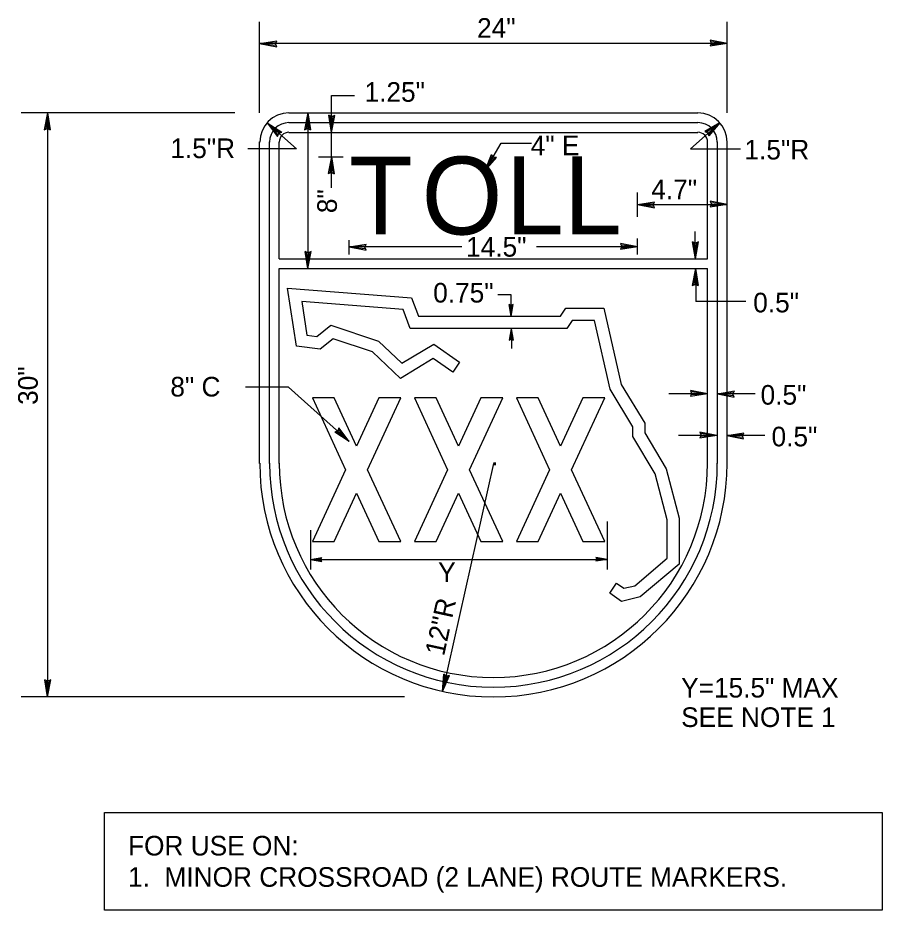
# Model space of a CAD drawing. Extents: x 52194 to 54069, y 8993 to 10153.
# Drawn here: x 52359.7 to 52729.7, y 9460.7 to 9842.7 of the extents above; entities that cross this region are included whole.
import ezdxf

# ---------------------------------------------------------------- set-up
doc = ezdxf.new("R2010")
doc.units = 0
for name, color, linetype in [('GSDims', 7, 'Continuous'), ('SignPanel', 7, 'Continuous'), ('TextLabel', 7, 'Continuous')]:
    doc.layers.add(name, color=color, linetype=linetype)

msp = doc.modelspace()

# ---------------------------------------------------------------- linework, layer by layer
at = {"layer": 'GSDims'}
for p, q in [((52463.23, 9802.06), (52463.23, 9840.96)), ((52663.33, 9802.06), (52663.33, 9840.96)), ((52463.23, 9831.66), (52470.53, 9832.86)), ((52463.23, 9831.66), (52470.23, 9832.16)), ((52663.33, 9831.66), (52463.23, 9831.66)), ((52463.23, 9831.66), (52470.53, 9830.26)), ((52463.23, 9831.66), (52470.23, 9830.96)), ((52470.03, 9831.56), (52470.53, 9832.86)), ((52470.53, 9830.26), (52470.03, 9831.56)), ((52663.33, 9831.66), (52656.03, 9833.06)), ((52656.03, 9833.06), (52656.53, 9831.76)), ((52656.53, 9831.76), (52656.03, 9830.56)), ((52663.33, 9831.66), (52656.03, 9830.56)), ((52663.33, 9831.66), (52656.33, 9832.46)), ((52663.33, 9831.66), (52656.33, 9831.16)), ((52493.98, 9793.66), (52493.98, 9809.41)), ((52493.98, 9809.41), (52503.83, 9809.41)), ((52452.58, 9802.06), (52361.21, 9802.06)), ((52372.46, 9802.06), (52371.06, 9794.81)), ((52372.46, 9802.06), (52371.71, 9795.06)), ((52372.46, 9802.06), (52372.46, 9552.01)), ((52372.46, 9802.06), (52373.61, 9794.76)), ((52372.46, 9802.06), (52372.96, 9795.06)), ((52483.83, 9802.06), (52482.43, 9794.81)), ((52483.83, 9802.06), (52483.08, 9795.06)), ((52483.83, 9802.06), (52483.83, 9735.36)), ((52483.83, 9802.06), (52484.98, 9794.76)), ((52483.83, 9802.06), (52484.33, 9795.06)), ((52493.98, 9793.66), (52492.83, 9800.96)), ((52494.08, 9800.41), (52492.83, 9800.96)), ((52493.98, 9793.66), (52495.38, 9800.91)), ((52495.38, 9800.91), (52494.08, 9800.41)), ((52663.33, 9802.06), (52663.33, 9802.06)), ((52466.43, 9797.81), (52478.98, 9786.66)), ((52466.43, 9797.81), (52472.68, 9793.81)), ((52466.43, 9797.81), (52470.93, 9791.91)), ((52466.43, 9797.81), (52471.18, 9792.61)), ((52466.43, 9797.81), (52471.98, 9793.51)), ((52466.43, 9797.81), (52472.68, 9793.81)), ((52466.43, 9797.81), (52470.93, 9791.91)), ((52466.43, 9797.81), (52471.18, 9792.61)), ((52466.43, 9797.81), (52471.98, 9793.51)), ((52493.98, 9793.66), (52493.48, 9800.66)), ((52493.98, 9793.66), (52494.73, 9800.66)), ((52660.13, 9797.81), (52647.58, 9786.66)), ((52660.13, 9797.81), (52653.78, 9794.06)), ((52660.13, 9797.81), (52654.43, 9793.71)), ((52660.13, 9797.81), (52655.23, 9792.81)), ((52660.13, 9797.81), (52655.43, 9792.11)), ((52371.06, 9794.81), (52372.36, 9795.31)), ((52372.36, 9795.31), (52373.61, 9794.76)), ((52470.93, 9791.91), (52471.38, 9793.26)), ((52470.93, 9791.91), (52471.38, 9793.26)), ((52471.38, 9793.26), (52472.68, 9793.81)), ((52471.38, 9793.26), (52472.68, 9793.81)), ((52482.43, 9794.81), (52483.73, 9795.31)), ((52483.73, 9795.31), (52484.98, 9794.76)), ((52493.98, 9783.26), (52493.98, 9793.66)), ((52653.78, 9794.06), (52655.03, 9793.41)), ((52655.03, 9793.41), (52655.43, 9792.11)), ((52478.98, 9786.66), (52458.13, 9786.66)), ((52559.78, 9777.31), (52566.63, 9789.11)), ((52566.63, 9789.11), (52579.61, 9789.11)), ((52647.58, 9786.66), (52669.08, 9786.66)), ((52488.48, 9783.26), (52498.93, 9783.26)), ((52493.98, 9783.26), (52492.58, 9776.01)), ((52493.98, 9783.26), (52493.23, 9776.26)), ((52493.98, 9769.96), (52493.98, 9783.26)), ((52493.98, 9783.26), (52495.13, 9775.96)), ((52493.98, 9783.26), (52494.48, 9776.26)), ((52559.78, 9777.31), (52562.43, 9784.21)), ((52559.78, 9777.31), (52562.88, 9783.61)), ((52559.78, 9777.31), (52563.93, 9782.96)), ((52559.78, 9777.31), (52564.63, 9782.91)), ((52563.28, 9783.06), (52562.43, 9784.21)), ((52564.63, 9782.91), (52563.28, 9783.06)), ((52492.58, 9776.01), (52493.88, 9776.51)), ((52493.88, 9776.51), (52495.13, 9775.96)), ((52624.93, 9757.51), (52624.93, 9767.96)), ((52624.93, 9762.76), (52632.23, 9763.91)), ((52624.93, 9762.76), (52631.93, 9763.26)), ((52624.93, 9762.76), (52663.33, 9762.76)), ((52624.93, 9762.76), (52632.18, 9761.36)), ((52624.93, 9762.76), (52631.93, 9762.01)), ((52631.68, 9762.66), (52632.23, 9763.91)), ((52632.18, 9761.36), (52631.68, 9762.66)), ((52656.58, 9762.86), (52656.03, 9761.61)), ((52663.33, 9762.76), (52656.03, 9761.61)), ((52663.33, 9762.76), (52656.08, 9764.16)), ((52656.08, 9764.16), (52656.58, 9762.86)), ((52663.33, 9762.76), (52656.33, 9763.51)), ((52663.33, 9762.76), (52656.33, 9762.26)), ((52501.53, 9741.36), (52501.53, 9747.56)), ((52624.93, 9741.36), (52624.93, 9748.26)), ((52649.78, 9739.51), (52649.68, 9751.16)), ((52501.53, 9744.66), (52508.83, 9745.81)), ((52501.53, 9744.66), (52508.53, 9745.16)), ((52501.53, 9744.66), (52508.78, 9743.26)), ((52501.53, 9744.66), (52508.53, 9743.91)), ((52549.76, 9744.66), (52501.53, 9744.66)), ((52508.28, 9744.56), (52508.83, 9745.81)), ((52508.78, 9743.26), (52508.28, 9744.56)), ((52624.93, 9744.66), (52581.72, 9744.66)), ((52618.18, 9744.76), (52617.63, 9743.51)), ((52624.93, 9744.66), (52617.63, 9743.51)), ((52624.93, 9744.66), (52617.68, 9746.06)), ((52617.68, 9746.06), (52618.18, 9744.76)), ((52624.93, 9744.66), (52617.93, 9745.41)), ((52624.93, 9744.66), (52617.93, 9744.16)), ((52649.78, 9739.51), (52648.48, 9746.81)), ((52649.78, 9746.21), (52648.48, 9746.81)), ((52649.78, 9739.51), (52649.18, 9746.51)), ((52649.78, 9739.51), (52651.08, 9746.81)), ((52651.08, 9746.81), (52649.78, 9746.21)), ((52649.78, 9739.51), (52650.38, 9746.51)), ((52483.83, 9735.36), (52482.68, 9742.66)), ((52483.93, 9742.11), (52482.68, 9742.66)), ((52483.83, 9735.36), (52483.33, 9742.36)), ((52483.83, 9735.36), (52485.23, 9742.61)), ((52483.83, 9735.36), (52484.58, 9742.36)), ((52485.23, 9742.61), (52483.93, 9742.11)), ((52649.78, 9735.36), (52648.38, 9728.06)), ((52649.78, 9735.36), (52649.08, 9728.36)), ((52649.78, 9735.36), (52650.98, 9728.06)), ((52649.78, 9735.36), (52650.28, 9728.36)), ((52649.78, 9735.36), (52649.93, 9721.26)), ((52648.38, 9728.06), (52649.68, 9728.56)), ((52649.68, 9728.56), (52650.98, 9728.06)), ((52570.88, 9724.16), (52565.13, 9724.16)), ((52570.88, 9715.01), (52570.88, 9724.16)), ((52671.38, 9721.26), (52649.93, 9721.26)), ((52570.88, 9715.01), (52570.08, 9719.91)), ((52570.88, 9719.51), (52570.08, 9719.91)), ((52570.88, 9715.01), (52570.48, 9719.71)), ((52570.88, 9715.01), (52571.78, 9719.91)), ((52571.78, 9719.91), (52570.88, 9719.51)), ((52570.88, 9715.01), (52571.28, 9719.71)), ((52570.88, 9709.61), (52569.98, 9704.71)), ((52570.88, 9709.61), (52570.48, 9704.91)), ((52570.88, 9709.61), (52570.98, 9701.21)), ((52570.88, 9709.61), (52571.68, 9704.71)), ((52570.88, 9709.61), (52571.28, 9704.91)), ((52569.98, 9704.71), (52570.88, 9705.11)), ((52570.88, 9705.11), (52571.68, 9704.71)), ((52475.63, 9684.55), (52457.23, 9684.55)), ((52501.59, 9661.29), (52475.63, 9684.55)), ((52654.93, 9681.76), (52647.63, 9683.16)), ((52647.63, 9683.16), (52648.13, 9681.86)), ((52654.93, 9681.76), (52647.93, 9682.56)), ((52659.13, 9681.76), (52666.43, 9682.96)), ((52665.83, 9681.66), (52666.43, 9682.96)), ((52654.93, 9681.76), (52638.43, 9681.76)), ((52648.13, 9681.86), (52647.63, 9680.66)), ((52654.93, 9681.76), (52647.63, 9680.66)), ((52654.93, 9681.76), (52647.93, 9681.26)), ((52659.13, 9681.76), (52666.13, 9682.26)), ((52659.13, 9681.76), (52666.33, 9680.36)), ((52659.13, 9681.76), (52666.13, 9681.06)), ((52675.38, 9681.76), (52659.13, 9681.76)), ((52666.33, 9680.36), (52665.83, 9681.66)), ((52497.12, 9667.19), (52496.66, 9665.87)), ((52501.59, 9661.29), (52497.12, 9667.19)), ((52496.66, 9665.87), (52495.38, 9665.31)), ((52501.59, 9661.29), (52495.38, 9665.31)), ((52501.59, 9661.29), (52496.05, 9665.6)), ((52501.59, 9661.29), (52496.88, 9666.5)), ((52658.98, 9663.91), (52642.48, 9663.91)), ((52658.98, 9663.91), (52651.68, 9665.31)), ((52651.68, 9665.31), (52652.18, 9664.01)), ((52652.18, 9664.01), (52651.68, 9662.81)), ((52658.98, 9663.91), (52651.68, 9662.81)), ((52658.98, 9663.91), (52651.98, 9664.71)), ((52658.98, 9663.91), (52651.98, 9663.41)), ((52663.18, 9663.91), (52670.48, 9665.11)), ((52663.18, 9663.91), (52670.18, 9664.41)), ((52663.18, 9663.91), (52670.38, 9662.51)), ((52663.18, 9663.91), (52670.18, 9663.21)), ((52679.43, 9663.91), (52663.18, 9663.91)), ((52669.88, 9663.81), (52670.48, 9665.11)), ((52670.38, 9662.51), (52669.88, 9663.81)), ((52563.33, 9651.96), (52541.53, 9554.36)), ((52563.33, 9651.96), (52563.33, 9651.96)), ((52611.96, 9627.06), (52611.96, 9606.57)), ((52484.99, 9623.44), (52484.99, 9606.57)), ((52484.99, 9610.88), (52489.86, 9611.63)), ((52484.99, 9610.88), (52489.66, 9611.19)), ((52484.99, 9610.88), (52489.86, 9610)), ((52484.99, 9610.88), (52489.66, 9610.44)), ((52484.99, 9610.88), (52538.09, 9610.88)), ((52489.46, 9610.82), (52489.86, 9611.63)), ((52489.86, 9610), (52489.46, 9610.82)), ((52538.09, 9610.88), (52611.96, 9610.88)), ((52611.96, 9610.88), (52607.09, 9611.75)), ((52607.09, 9611.75), (52607.49, 9610.94)), ((52607.49, 9610.94), (52607.09, 9610.13)), ((52611.96, 9610.88), (52607.09, 9610.13)), ((52611.96, 9610.88), (52607.29, 9611.32)), ((52611.96, 9610.88), (52607.29, 9610.57)), ((52541.53, 9554.36), (52542.03, 9561.76)), ((52541.53, 9554.36), (52542.63, 9561.36)), ((52541.53, 9554.36), (52544.53, 9561.16)), ((52541.53, 9554.36), (52543.83, 9561.06)), ((52543.13, 9560.96), (52542.03, 9561.76)), ((52544.53, 9561.16), (52543.13, 9560.96)), ((52372.46, 9552.01), (52371.31, 9559.31)), ((52372.56, 9558.76), (52371.31, 9559.31)), ((52372.46, 9552.01), (52371.96, 9559.01)), ((52372.46, 9552.01), (52373.86, 9559.26)), ((52372.46, 9552.01), (52373.21, 9559.01)), ((52373.86, 9559.26), (52372.56, 9558.76)), ((52525.18, 9552.01), (52361.21, 9552.01))]:
    msp.add_line(p, q, dxfattribs=at)
at = {"layer": 'SignPanel'}
for p, q in [((52475.73, 9802.06), (52650.83, 9802.06)), ((52475.73, 9797.86), (52650.83, 9797.86)), ((52475.73, 9793.66), (52650.83, 9793.66)), ((52463.23, 9651.96), (52463.23, 9789.56)), ((52467.43, 9651.96), (52467.43, 9789.56)), ((52471.53, 9739.56), (52471.53, 9789.56)), ((52654.93, 9739.56), (52654.93, 9789.56)), ((52659.13, 9651.96), (52659.13, 9789.56)), ((52663.33, 9651.96), (52663.33, 9789.56)), ((52471.53, 9739.56), (52654.93, 9739.56)), ((52471.53, 9651.96), (52471.53, 9735.36)), ((52471.53, 9735.36), (52654.93, 9735.36)), ((52654.93, 9651.96), (52654.93, 9735.36)), ((52475.21, 9726.98), (52528.21, 9722.78)), ((52478.98, 9702.13), (52475.21, 9726.98)), ((52524.61, 9717.81), (52481.25, 9721.24)), ((52481.25, 9721.24), (52483.44, 9706.84)), ((52528.21, 9722.78), (52531.17, 9714.97)), ((52527.68, 9709.73), (52524.61, 9717.81)), ((52591.96, 9714.97), (52594.25, 9718.44)), ((52594.25, 9718.44), (52610.61, 9718.44)), ((52610.61, 9718.44), (52618.01, 9685.78)), ((52531.17, 9714.97), (52591.96, 9714.97)), ((52596.97, 9713.2), (52594.68, 9709.73)), ((52606.55, 9713.2), (52596.97, 9713.2)), ((52613.23, 9683.75), (52606.55, 9713.2)), ((52487.64, 9706.31), (52493.66, 9711.17)), ((52493.66, 9711.17), (52514.11, 9704.35)), ((52594.68, 9709.73), (52527.68, 9709.73)), ((52483.44, 9706.84), (52487.64, 9706.31)), ((52489.13, 9700.84), (52478.98, 9702.13)), ((52494.68, 9705.32), (52489.13, 9700.84)), ((52511.46, 9699.72), (52494.68, 9705.32)), ((52514.11, 9704.35), (52524.15, 9694.82)), ((52524.15, 9694.82), (52537.75, 9703.01)), ((52537.75, 9703.01), (52548.82, 9695.34)), ((52523.46, 9688.33), (52511.46, 9699.72)), ((52537.56, 9696.82), (52523.46, 9688.33)), ((52545.96, 9691), (52537.56, 9696.82)), ((52548.82, 9695.34), (52545.96, 9691)), ((52622.98, 9667.68), (52613.23, 9683.75)), ((52618.01, 9685.78), (52628.09, 9669.18)), ((52495.12, 9680), (52485.78, 9680)), ((52485.78, 9680), (52500.03, 9649.27)), ((52504.69, 9659.35), (52495.12, 9680)), ((52514.27, 9680), (52504.69, 9659.35)), ((52509.36, 9649.27), (52523.61, 9680)), ((52523.61, 9680), (52514.27, 9680)), ((52538.78, 9680), (52529.44, 9680)), ((52529.44, 9680), (52543.68, 9649.27)), ((52548.35, 9659.35), (52538.78, 9680)), ((52557.93, 9680), (52548.35, 9659.35)), ((52553.02, 9649.27), (52567.27, 9680)), ((52567.27, 9680), (52557.93, 9680)), ((52582.44, 9680), (52573.1, 9680)), ((52573.1, 9680), (52587.34, 9649.27)), ((52592.01, 9659.35), (52582.44, 9680)), ((52601.59, 9680), (52592.01, 9659.35)), ((52596.68, 9649.27), (52610.93, 9680)), ((52610.93, 9680), (52601.59, 9680)), ((52622.98, 9663.52), (52622.98, 9667.68)), ((52628.09, 9669.18), (52628.09, 9664.99)), ((52632.47, 9647.51), (52622.98, 9663.52)), ((52628.09, 9664.99), (52637.21, 9649.6)), ((52500.03, 9649.27), (52485.78, 9618.54)), ((52523.61, 9618.54), (52509.36, 9649.27)), ((52543.68, 9649.27), (52529.44, 9618.54)), ((52567.27, 9618.54), (52553.02, 9649.27)), ((52587.34, 9649.27), (52573.1, 9618.54)), ((52610.93, 9618.54), (52596.68, 9649.27)), ((52637.21, 9649.6), (52642.83, 9628.54)), ((52637.72, 9627.84), (52632.47, 9647.51)), ((52495.12, 9618.54), (52504.7, 9639.2)), ((52504.7, 9639.2), (52514.27, 9618.54)), ((52538.78, 9618.54), (52548.35, 9639.2)), ((52548.35, 9639.2), (52557.93, 9618.54)), ((52582.44, 9618.54), (52592.01, 9639.2)), ((52592.01, 9639.2), (52601.59, 9618.54)), ((52637.72, 9611.35), (52637.72, 9627.84)), ((52642.83, 9628.54), (52642.83, 9608.87)), ((52485.78, 9618.54), (52495.12, 9618.54)), ((52514.27, 9618.54), (52523.61, 9618.54)), ((52529.44, 9618.54), (52538.78, 9618.54)), ((52557.93, 9618.54), (52567.27, 9618.54)), ((52573.1, 9618.54), (52582.44, 9618.54)), ((52601.59, 9618.54), (52610.93, 9618.54)), ((52623.76, 9599.62), (52637.72, 9611.35)), ((52642.83, 9608.87), (52626.09, 9594.81)), ((52613.1, 9596.44), (52616.01, 9600.74)), ((52616.01, 9600.74), (52619.17, 9598.5)), ((52619.17, 9598.5), (52623.76, 9599.62)), ((52618.14, 9592.85), (52613.1, 9596.44)), ((52626.09, 9594.81), (52618.14, 9592.85))]:
    msp.add_line(p, q, dxfattribs=at)
for centre, radius, start, end in [((52475.78, 9789.51), 12.5, 90, 180), ((52650.78, 9789.51), 12.5, 0, 90), ((52475.78, 9789.51), 8.33, 90, 180), ((52650.78, 9789.51), 8.33, 0, 90), ((52475.78, 9789.51), 4.17, 90, 180), ((52650.78, 9789.51), 4.17, 0, 90), ((52563.28, 9652.01), 100, 180, 0), ((52563.28, 9652.01), 95.83, 180, 0), ((52563.28, 9652.01), 91.67, 180, 0)]:
    msp.add_arc(centre, radius, start, end, dxfattribs=at)
at = {"layer": 'TextLabel'}
msp.add_lwpolyline([(52396.89, 9502.53), (52729.67, 9502.53), (52729.67, 9460.73), (52396.89, 9460.73)], close=True, dxfattribs=at)

# ---------------------------------------------------------------- texts
at = {"layer": 'GSDims'}
for s, p in [('24"', (52556.29, 9834.16)), ('1.25"', (52508.13, 9806.76)), ('1.5"R', (52425, 9782.65)), ('4" E', (52579.25, 9783.86)), ('1.5"R', (52670.75, 9782.06)), ('4.7"', (52630.87, 9765.06)), ('14.5"', (52551.59, 9740.47)), ('0.75"', (52537.51, 9720.81)), ('0.5"', (52674.49, 9716.61)), ('8" C', (52424.99, 9680.6)), ('0.5"', (52677.64, 9677.11)), ('0.5"', (52682.33, 9659.26)), ('.', (52562.27, 9651.17)), ('Y', (52539.62, 9601.15)), ('Y=15.5" MAX', (52643.64, 9551.74)), ('SEE NOTE 1', (52643.64, 9539.14))]:
    msp.add_text(s, height=8.4, dxfattribs=at).set_placement(p)
for s, rotation, p in [('8"', 90, (52496.29, 9759.08)), ('30"', 90, (52368.25, 9677.01)), ('12"R', 77.7352, (52542.13, 9569.19))]:
    msp.add_text(s, height=8.4, rotation=rotation, dxfattribs=at).set_placement(p)
at = {"layer": 'SignPanel'}
for s, p in [('T', (52501.53, 9749.96)), ('O', (52532.53, 9749.96)), ('LL', (52568.63, 9750.06))]:
    msp.add_text(s, height=33.3, dxfattribs=at).set_placement(p)
at = {"layer": 'TextLabel'}
for s, p in [('FOR USE ON:', (52406.89, 9484.13)), ('1.  MINOR CROSSROAD (2 LANE) ROUTE MARKERS.', (52406.89, 9470.73))]:
    msp.add_text(s, height=8.4, dxfattribs=at).set_placement(p)

doc.saveas('drawing.dxf')
